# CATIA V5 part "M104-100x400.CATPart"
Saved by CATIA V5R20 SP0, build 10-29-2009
Part number: M104-100x400
Source: Unknown
Bounding box of the stored display mesh (mm): x -49.986 to 49.986, y -49.986 to 49.986, z 0 to 400
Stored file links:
  C:\Users\Utente\Desktop\IO LAVORO\3D X SITO CF\X SITO\M104\M104-100x400.CATPart

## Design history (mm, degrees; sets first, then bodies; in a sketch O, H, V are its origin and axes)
Body1 (main body)
  Solid1 "PartBody": solid without history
